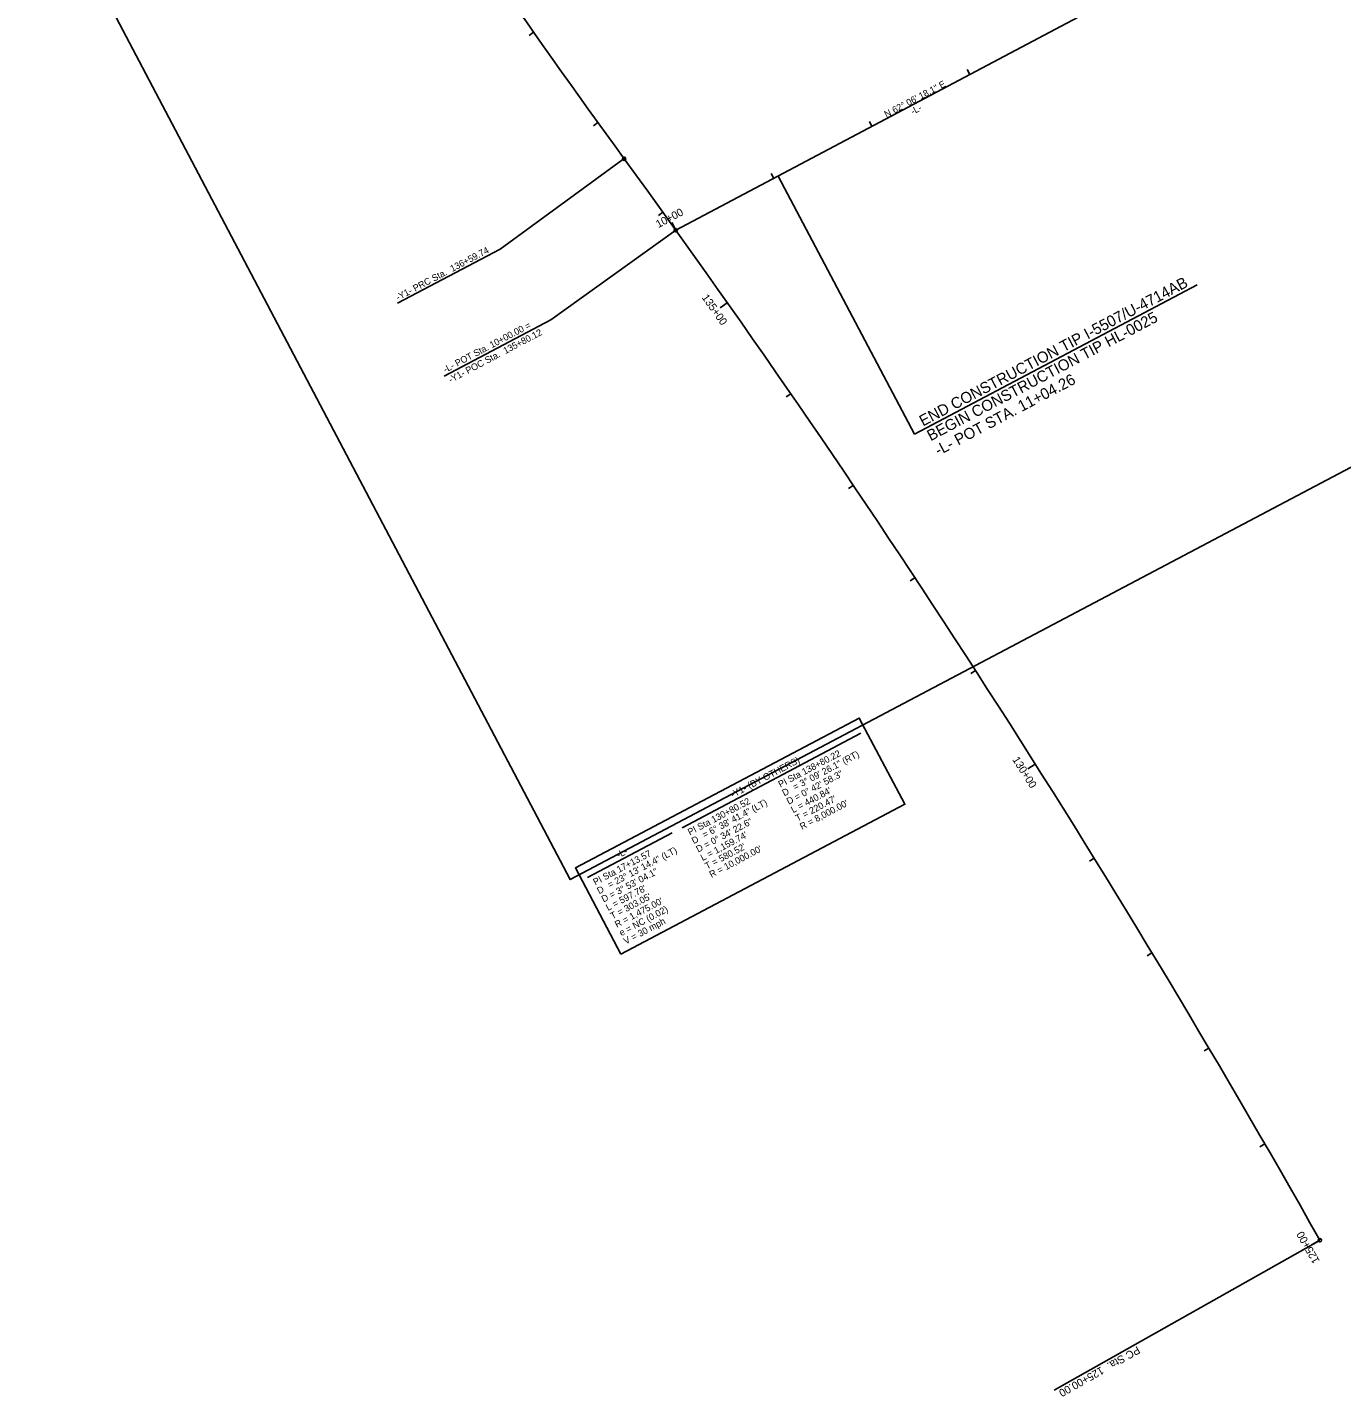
# Model space of a CAD drawing. Extents: x 1487008 to 1489561, y 497293 to 500195.
# Drawn here: x 1487168 to 1488352, y 497293 to 498527 of the extents above; entities that cross this region are included whole.
import ezdxf

# ---------------------------------------------------------------- set-up
doc = ezdxf.new("R2010")
doc.units = 0
for name, color, linetype in [('Prop Grid Mask', 7, 'Continuous'), ('Prop Horizontal Alignment', 7, 'Continuous'), ('Prop Horizontal Alignment Curve and Spiral Data', 7, 'Continuous'), ('Prop Horizontal Alignment Direction Label', 7, 'Continuous'), ('Prop Horizontal Alignment Station Label', 7, 'Continuous'), ('Prop Horizontal Alignment Tick Label', 7, 'Continuous'), ('Prop Horizontal Alignment Tick Large', 7, 'Continuous'), ('Prop Horizontal Alignment Tick Small', 7, 'Continuous'), ('Scratch_Level_5', 7, 'Continuous')]:
    doc.layers.add(name, color=color, linetype=linetype)

msp = doc.modelspace()

# ---------------------------------------------------------------- linework, layer by layer
at = {"layer": 'Prop Grid Mask'}
msp.add_lwpolyline([(1487702.7, 497691.7), (1487958.7, 497826.8), (1487917.6, 497904.5), (1487661.7, 497769.4)], close=True, dxfattribs=at)
at = {"layer": 'Prop Horizontal Alignment'}
msp.add_line((1487752.2, 498344.1), (1488115, 498536.2), dxfattribs=at)
for centre, radius, start, end in [((1494171.2, 503119.9), 8000, 212.92217, 216.07943), ((1479623.6, 492519.6), 10000, 29.43458, 36.07943)]:
    msp.add_arc(centre, radius, start, end, dxfattribs=at)
at = {"layer": 'Prop Horizontal Alignment Curve and Spiral Data'}
for p, q in [((1487757.8, 497805.7), (1487919, 497890.9)), ((1487672.5, 497760.7), (1487748.8, 497801))]:
    msp.add_line(p, q, dxfattribs=at)
at = {"layer": 'Prop Horizontal Alignment Station Label'}
for p, q in [((1487704.4, 498407.8), (1487593.9, 498327.2)), ((1487844.4, 498392.9), (1487967.5, 498160.4)), ((1487752.2, 498344.1), (1487639.6, 498263.4)), ((1487501.2, 498278.3), (1487593.9, 498327.2)), ((1487967.5, 498160.4), (1488222.2, 498294.9)), ((1487543.4, 498212.6), (1487639.6, 498263.4)), ((1488331.5, 497433.1), (1488093.3, 497298.7))]:
    msp.add_line(p, q, dxfattribs=at)
for centre in [(1487705.6, 498408.6), (1487752.2, 498344.1), (1488332.8, 497433.9)]:
    msp.add_circle(centre, 1.5, dxfattribs=at)
at = {"layer": 'Prop Horizontal Alignment Tick Large'}
for p, q in [((1487752.2, 498344.1), (1487748.5, 498351.2)), ((1487798.6, 498278.8), (1487792.1, 498274.2)), ((1488076.3, 497863), (1488069.5, 497858.7)), ((1488332.8, 497433.9), (1488325.8, 497429.9))]:
    msp.add_line(p, q, dxfattribs=at)
at = {"layer": 'Prop Horizontal Alignment Tick Small'}
for p, q in [((1487624, 498522.7), (1487619.9, 498519.8)), ((1488017.4, 498484.5), (1488015, 498488.9)), ((1487682, 498441.2), (1487677.9, 498438.3)), ((1487929, 498437.7), (1487926.7, 498442.1)), ((1487840.6, 498390.9), (1487838.3, 498395.3)), ((1487740.6, 498360.3), (1487736.6, 498357.3)), ((1487855.8, 498196.8), (1487851.7, 498193.9)), ((1487912.2, 498114.2), (1487908, 498111.4)), ((1487967.7, 498031), (1487963.5, 498028.2)), ((1488022.4, 497947.3), (1488018.2, 497944.6)), ((1488129.3, 497778.2), (1488125, 497775.6)), ((1488181.4, 497692.9), (1488177.2, 497690.3)), ((1488232.7, 497607.1), (1488228.4, 497604.5)), ((1488283.2, 497520.7), (1488278.8, 497518.2))]:
    msp.add_line(p, q, dxfattribs=at)
at = {"layer": 'Scratch_Level_5'}
msp.add_lwpolyline([(1488170.1, 499217.2), (1487167.7, 498687.9), (1487657.1, 497758.9), (1488983.5, 498459.3), (1488907.6, 498603.2)], dxfattribs=at)

# ---------------------------------------------------------------- texts
at = {"layer": 'Prop Horizontal Alignment Curve and Spiral Data'}
for s, p in [('PI Sta 138+80.22', (1487846.5, 497841.7)), ('= 3%%d 09\' 26.1" (RT)', (1487859.7, 497839.2)), ('-Y1- (BY OTHERS)', (1487803.5, 497832.4)), ('D = 0%%d 42\' 58.3"', (1487854, 497826.3)), ('D', (1487850, 497833.9)), ("L = 440.84'", (1487858, 497818.7)), ('PI Sta 130+80.52', (1487764.9, 497798.6)), ('= 6%%d 38\' 41.4" (LT)', (1487778, 497796.1)), ("T = 220.47'", (1487862, 497811.1)), ("R = 8,000.00'", (1487866, 497803.6)), ('D = 0%%d 34\' 22.6"', (1487772.4, 497783.2)), ("L = 1,159.74'", (1487776.4, 497775.6)), ('= 23%%d 13\' 14.4" (LT)', (1487692.7, 497751.1)), ('D', (1487768.4, 497790.8)), ("T = 580.52'", (1487780.4, 497768)), ("R = 10,000.00'", (1487784.4, 497760.4)), ('PI Sta 17+13.57', (1487679.6, 497753.6)), ('-L-', (1487700.7, 497778.1)), ('D = 3%%d 53\' 04.1"', (1487687.1, 497738.2)), ('D', (1487683.1, 497745.7)), ("L = 597.78'", (1487691.1, 497730.6)), ("T = 303.05'", (1487695.1, 497723)), ("R = 1,475.00'", (1487699.1, 497715.4)), ('e = NC (0.02)', (1487703.1, 497707.8)), ('V = 30 mph', (1487707.1, 497700.3))]:
    msp.add_text(s, height=6, rotation=27.8351, dxfattribs=at).set_placement(p)
at = {"layer": 'Prop Horizontal Alignment Direction Label'}
for s, p in [('N 62%%d 06\' 18.1" E', (1487942.1, 498445.5)), ('-L-', (1487965.9, 498448.1))]:
    msp.add_text(s, height=6, rotation=27.895, dxfattribs=at).set_placement(p)
at = {"layer": 'Prop Horizontal Alignment Station Label'}
for s, height, rotation, p in [('-Y1- PRC Sta.  136+59.74', 6, 27.8351, (1487501.8, 498280.6)), ('END CONSTRUCTION TIP I-5507/U-4714AB', 10, 27.8351, (1487975, 498167.2)), ('BEGIN CONSTRUCTION TIP HL-0025', 10, 27.8351, (1487982, 498153.9)), ('-L- POT Sta. 10+00.00 =', 6, 27.8351, (1487544.5, 498215.6)), ('-Y1- POC Sta.  135+80.12', 6, 27.8351, (1487549.3, 498206.4)), ('-L- POT STA. 11+04.26', 10, 27.8351, (1487989, 498140.7)), ('PC Sta.  125+00.00', 7, 209.4346, (1488168.2, 497338.7))]:
    msp.add_text(s, height=height, rotation=rotation, dxfattribs=at).set_placement(p)
at = {"layer": 'Prop Horizontal Alignment Tick Label'}
for s, rotation, p in [('10+00', 27.895, (1487736.5, 498346)), ('135+00', 305.1642, (1487775.3, 498283.5)), ('130+00', 302.2994, (1488055.3, 497867.1)), ('125+00', 119.4346, (1488332.9, 497415.3))]:
    msp.add_text(s, height=7, rotation=rotation, dxfattribs=at).set_placement(p)

doc.saveas('drawing.dxf')
